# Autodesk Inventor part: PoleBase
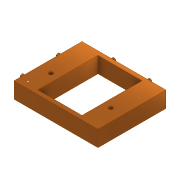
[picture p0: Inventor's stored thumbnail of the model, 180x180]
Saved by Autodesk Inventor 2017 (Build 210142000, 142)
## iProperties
Part Number: PoleBase
Material: ゴールド
Document SubType Name: Modeling
Designer: kyushu-hep
Density: 19.3 g/cm^3
Appearance: メタル 1600F 熱
Author: kyushu-hep
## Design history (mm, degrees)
sketch "スケッチ1"
  geometry: L1 (-9.744, 77.452)-(95.256, 77.452); L2 (95.256, 77.452)-(95.256, -7.548); L3 (95.256, -7.548)-(-9.744, -7.548); L4 (-9.744, -7.548)-(-9.744, 77.452); 1 further point
  constraints: 8 end point, 2 parallel, 1 horizontal, 1 perpendicular
  dimensions: "d0" = 105 distance of L2.end L3.end; "d1" = 85 distance of L3.end L1.start
extrude "押し出し1" new body sketch "スケッチ1" distance "d2" = 20; taper "d3" = 0 deg
sketch "スケッチ2"
  geometry: L1 (15.256, 72.452)-(70.256, 72.452); L2 (70.256, 72.452)-(70.256, -2.548); L3 (70.256, -2.548)-(15.256, -2.548); L4 (15.256, -2.548)-(15.256, 72.452); L5 (-9.744, -7.548)-(95.256, -7.548) reference; L6 (-9.744, 77.452)-(-9.744, -7.548) reference; 1 further point
  constraints: 8 end point, 2 parallel, 1 horizontal, 1 perpendicular
  dimensions: "d4" = 55 distance of L2.end L3.end; "d5" = 75 distance of L3.end L1.start; "d6" = 5 distance between parallel lines of L5 L3; "d7" = 25 distance between parallel lines of L6 L4
extrude "押し出し2" cut sketch "スケッチ2" distance "d8" = 20; taper "d9" = 0 deg
sketch "スケッチ3"
  geometry: L1 (0, 0)-(20, 0) reference; L2 (20, 5)-(20, 80) reference; L3 (0, 85)-(20, 85) reference; C1 r 5 at (10, 20); C2 r 5 at (10, 65); 1 further point
  constraints: 2 centre point
  dimensions: "d10" = 10 diameter of C1; "d11" = 20 distance from line of L1 C1.centre; "d12" = 10 distance from line of L2 C1.centre; "d13" = 10 diameter of C2; "d14" = 10 distance from line of C2.centre L2; "d15" = 20 distance from line of C2.centre L3
extrude "押し出し3" cut sketch "スケッチ3" distance "d16" = 2; taper "d17" = 0 deg
sketch "スケッチ4"
  geometry: L1 (10, 20)-(10, -65) reference; L2 (-10, 20)-(10, 20) reference; L3 (-10, -65)-(10, -65) reference; C1 r 2.5 at (0, 0); C2 r 2.5 at (0, -45); 1 further point
  constraints: 2 centre point
  dimensions: "d18" = 5 diameter of C1; "d19" = 10 distance from line of C1.centre L1; "d20" = 20 distance from line of C1.centre L2; "d21" = 5 diameter of C2; "d22" = 10 distance from line of L1 C2.centre; "d23" = 20 distance from line of C2.centre L3
extrude "押し出し4" join sketch "スケッチ4" distance "d24" = 12; taper "d25" = 0 deg
sketch "スケッチ6"
  geometry: L1 (0, 0)-(105, 0) reference; L2 (105, 0)-(105, -20) reference; L3 (0, 0)-(0, -20) reference; C1 r 5 at (75, -10); C2 r 5 at (30, -10); 1 further point
  constraints: 2 centre point
  dimensions: "d34" = 10 diameter of C1; "d35" = 10 distance from line of C1.centre L1; "d36" = 30 distance from line of C1.centre L2; "d37" = 10 diameter of C2; "d38" = 10 distance from line of C2.centre L1; "d39" = 30 distance from line of C2.centre L3
extrude "押し出し6" cut sketch "スケッチ6" distance "d40" = 2; taper "d41" = 0 deg
sketch "スケッチ7"
  geometry: L1 (30, 10)-(30, -10) reference; L2 (-75, 10)-(-75, -10) reference; L3 (-75, 10)-(30, 10) reference; C1 r 2.5 at (0, 0); C2 r 2.5 at (-45, 0); 1 further point
  constraints: 2 centre point
  dimensions: "d42" = 5 diameter of C1; "d43" = 5 diameter of C2; "d44" = 30 distance from line of C1.centre L1; "d45" = 30 distance from line of L2 C2.centre; "d46" = 10 distance from line of L3 C2.centre; "d47" = 10 distance from line of L3 C1.centre
extrude "押し出し7" join sketch "スケッチ7" distance "d48" = 12; taper "d49" = 0 deg
sketch "スケッチ8"
  geometry: L1 (-9.744, 77.452)-(-9.744, -7.548) reference; L2 (-9.744, -7.548)-(95.256, -7.548) reference; L3 (95.256, -7.548)-(95.256, 77.452) reference; C1 r 2.5 at (5.256, 23.452); C2 r 2.5 at (80.256, 23.452); 1 further point
  constraints: 2 centre point
  dimensions: "d50" = 5 diameter of C1; "d51" = 15 distance from line of C1.centre L1; "d52" = 31 distance from line of C1.centre L2; "d53" = 5 diameter of C2; "d54" = 31 distance from line of L2 C2.centre; "d55" = 15 distance from line of L3 C2.centre
extrude "押し出し8" cut sketch "スケッチ8" stored distance "d56" = 50; taper "d57" = 0 deg
sketch "スケッチ9"
  geometry: 1 further point
node "ソリッド1"
